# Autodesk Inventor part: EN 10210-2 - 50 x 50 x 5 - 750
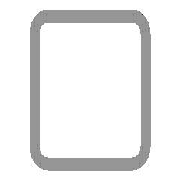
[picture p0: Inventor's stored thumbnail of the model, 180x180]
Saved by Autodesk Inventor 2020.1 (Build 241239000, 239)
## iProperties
Created: 2019-01
Part Number: EN 10210-2 - 50 x 50 x 5 - 750
Material: Stahl, weich
Description: Rohrleitung
Document SubType Name: Modeling
Standard: DIN
Designer: lutzd
Standard Revision: 2006-07
Standards Organization: DIN
Language: de-DE
Size Designation: 50 x 50 x 5
Categories: <MemberInstance><Categories><Category DisplayName="Profile" InternalName="089c4875-fa83-4c05-b084-43b9cc11f5ed" Mnemonic="GRDR"><CategoryParameter DisplayName="
Stock Number: 50 x 50 x 5
Mass: 5134.01 g
Surface Area: 2558.26 cm^2
Volume: 654.014 cm^3
Density: 7.85 g/cm^3
Appearance: Semi-Polished(8)
_CCFamilyMember: 16
_CCFamilyDisplayName: DIN EN 10210-2 (USAS B17.1 quadratisch) - Rohrleitung — In Klammern angegebene Größen wurden aufgehoben
_FrameMemberDoc: Frame Member File
_Version: 15.0.0
_GetPNFromCC: 1
IsCustomPart: 1
G_L: 750,000 mm
G_W: 50,000 mm
G_H: 50,000 mm
DocNumber: ADSK-014278
Folder: .
Dimensions: 50x50x750 mm
Mass: 5,134 kg
VLT_Material: Stahl, weich
Title: Profil-Bauteil
Author: lutzd
Revision Number: -
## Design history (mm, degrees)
node "Startebene"
node "Endebene"
sketch "Skizze"
  geometry: L1 (-25, -17.5)-(-25, 17.5); L2 (-17.5, 25)-(17.5, 25); L3 (25, 17.5)-(25, -17.5); L4 (17.5, -25)-(-17.5, -25); L5 (-15, 20)-(15, 20); L6 (20, 15)-(20, -15); L7 (15, -20)-(-15, -20); L8 (-20, -15)-(-20, 15); L9 (0, 37.175)-(0, -37.175) reference; L10 (-37.175, 0)-(37.175, 0) reference; A1 r 7.5 centre (-17.5, -17.5) between (-25, -17.5) and (-17.5, -25); A2 r 7.5 centre (-17.5, 17.5) between (-17.5, 25) and (-25, 17.5); A3 r 7.5 centre (17.5, 17.5) between (25, 17.5) and (17.5, 25); A4 r 7.5 centre (17.5, -17.5) between (17.5, -25) and (25, -17.5); A5 r 5 centre (-15, -15) between (-20, -15) and (-15, -20); A6 r 5 centre (-15, 15) between (-15, 20) and (-20, 15); A7 r 5 centre (15, 15) between (20, 15) and (15, 20); A8 r 5 centre (15, -15) between (15, -20) and (20, -15)
  constraints: 16 end point, 16 point on circle, 16 tangent, 8 centre point, 6 equal radius, 4 parallel, 2 perpendicular, 2 other
  dimensions: "d7" = 7.5 radius of A1 (= G_IR); "d10" = 50 distance between parallel lines of L2 L4 (= G_H); "d11" = 50 distance between parallel lines of L1 L3 (= G_W); "d12" = 5 distance between parallel lines of L3 L6 (= G_T); "d15" = 25 distance between parallel lines of L2 L10 (= 0.5 x d10); "d16" = 25 distance between parallel lines of L9 L3 (= 0.5 x d11); "d19" = 5 radius of A5 (= G_T); "d20" = 5 distance between parallel lines of L4 L7 (= G_T)
extrude "Körper" new body sketch "Skizze" stored distance "d3" = 750 (= G_L); taper "d4" = 0 deg
node "Driven Length"
  sketch "Sketch3"
    geometry: L1 (0, 0)-(10, 0) reference
    constraints: 2 end point, 1 horizontal
  workplane "Work Plane3"
  sketch "Sketch4"
    geometry: L1 (-2, 0)-(12, 0) reference; L2 (-2, 750)-(12, 750) reference
    dimensions: "d18" = 750 distance between parallel lines of L1 L2 (derived)
sketch "Skizze5"
  geometry: L1 (0, 35)-(0, 0) reference; L2 (0, 17.5)-(169, 17.5); 3 further points
  constraints: 2 end point, 1 coincident, 1 horizontal, 1 midpoint, 1 point on line
  dimensions: "d21" = 38 distance of point (169, 17.5) point (131, 17.5); "d22" = 131 distance from line of L1 point (131, 17.5)
hole "Bohrung1" sketch "Skizze5" at (169, 17.5), (131, 17.5) diameter "d23" = 6.647; stored, may be unused: countersink angle "d27" = 90 deg, drill point angle "d29" = 118 deg; dims "d24" = 16, "d25" = 4, "d26" = 2, "d28" = 8
sketch "Skizze7"
  geometry: L1 (-35, 0)-(0, 0) reference; L2 (-17.5, 0)-(-17.5, 52.35); 3 further points
  constraints: 2 end point, 1 coincident, 1 midpoint, 1 point on line, 1 vertical
  dimensions: "d39" = 14.35 distance from line of L1 point (-17.5, 14.35); "d40" = 38 distance of point (-17.5, 14.35) point (-17.5, 52.35)
hole "Bohrung3" sketch "Skizze7" at (-17.5, 52.35), (-17.5, 14.35) diameter "d41" = 6.647; stored, may be unused: countersink angle "d45" = 90 deg, drill point angle "d47" = 118 deg; dims "d42" = 16, "d43" = 17.3, "d44" = 2, "d46" = 22.2
sketch "Skizze8"
  geometry: L1 (750, -35)-(750, 0) reference; L2 (750, -17.5)-(447, -17.5); 2 further points
  constraints: 2 end point, 1 coincident, 1 horizontal, 1 midpoint
  dimensions: "d48" = 303 distance of L2.start L2.end
hole "Bohrung4" sketch "Skizze8" at (447, -17.5) diameter "d49" = 6.647; stored, may be unused: countersink angle "d53" = 90 deg, drill point angle "d55" = 118 deg; dims "d50" = 16, "d51" = 4, "d52" = 2, "d54" = 8
body "Solid1"
other parameters: "G_W" = 50 [user parameter; used in 1 equation term], "G_H" = 50 [user parameter; used in 1 equation term], "G_T" = 5 [user parameter; used in 3 equation terms], "G_IR" = 7.5 [user parameter; used in 1 equation term], "G_L" = 750 (= d18) [user parameter; used in 1 equation term], "G_OFFSET_START" = 0 [user parameter; used in 1 equation term], "G_OFFSET_END" = 0 [user parameter; used in 1 equation term], "d13" = 0 (computed from G_OFFSET_START), "d17" = 90 deg
